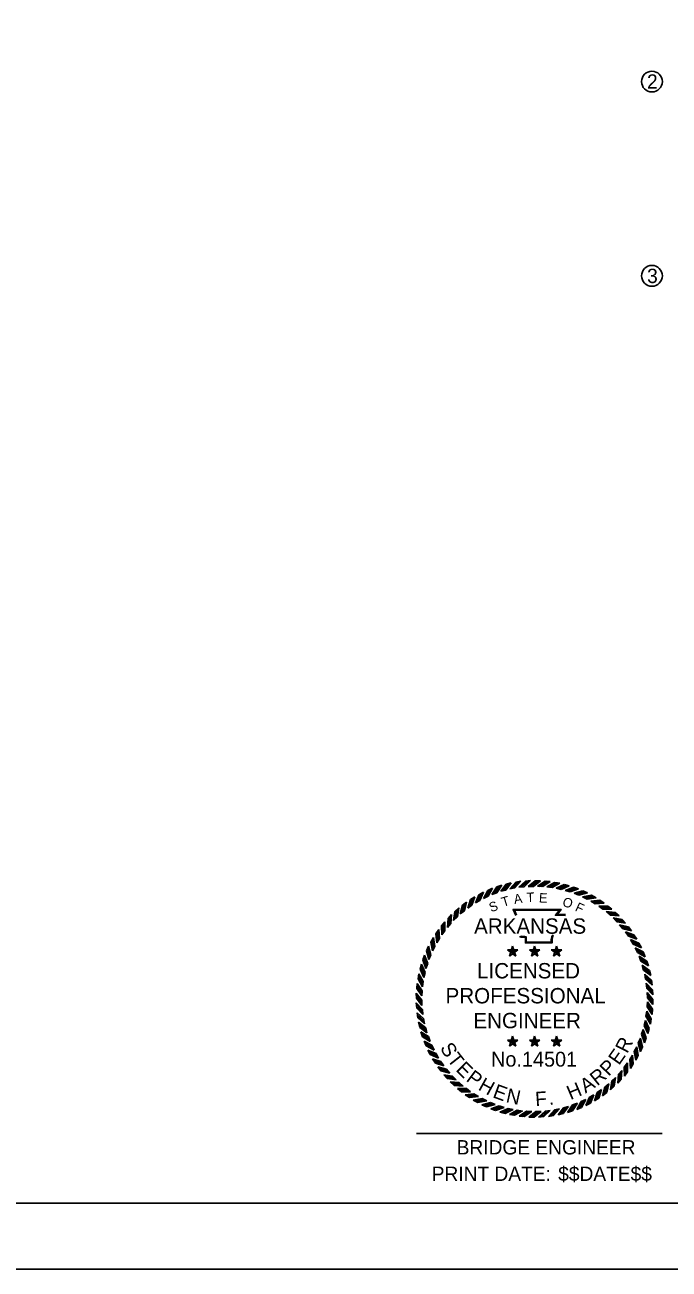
# Model space of a CAD drawing. Extents: x 188 to 14744886, y 129 to 1829278.
# Drawn here: x 208.75 to 214.37, y 128.51 to 139.38 of the extents above; entities that cross this region are included whole.
import ezdxf

# ---------------------------------------------------------------- set-up
doc = ezdxf.new("R2010")
doc.units = 0
for name, color, linetype in [('B_border', 7, 'Continuous'), ('B_Dimensions', 7, 'Continuous'), ('B_Print_Date_Text', 7, 'Continuous'), ('B_StampSFH', 7, 'Continuous'), ('B_Text', 7, 'Continuous'), ('R_Border', 7, 'Continuous'), ('R_No Plot', 7, 'Continuous')]:
    doc.layers.add(name, color=color, linetype=linetype)

msp = doc.modelspace()

# ---------------------------------------------------------------- linework, layer by layer
at = {"layer": 'B_border'}
msp.add_line((212.167, 129.699), (214.309, 129.699), dxfattribs=at)
msp.add_line((212.167, 129.699), (214.309, 129.699), dxfattribs=at)
at = {"layer": 'B_Dimensions'}
for centre in [(214.221, 138.883), (214.221, 137.187)]:
    msp.add_circle(centre, 0.0908, dxfattribs=at)
at = {"layer": 'B_StampSFH'}
for p, q in [((213.033, 131.892), (213.077, 131.9)), ((213.117, 131.902), (213.162, 131.906)), ((213.203, 131.905), (213.248, 131.905)), ((213.288, 131.901), (213.333, 131.898)), ((212.711, 131.783), (212.75, 131.805)), ((212.788, 131.82), (212.829, 131.839)), ((212.825, 131.785), (212.868, 131.8)), ((212.867, 131.851), (212.91, 131.866)), ((212.902, 131.813), (212.946, 131.824)), ((212.949, 131.875), (212.993, 131.886)), ((212.98, 131.834), (213.025, 131.842)), ((213.06, 131.848), (213.105, 131.853)), ((213.141, 131.856), (213.187, 131.856)), ((213.223, 131.858), (213.268, 131.854)), ((213.304, 131.852), (213.349, 131.845)), ((213.372, 131.89), (213.417, 131.883)), ((213.384, 131.84), (213.428, 131.829)), ((213.456, 131.872), (213.5, 131.862)), ((213.464, 131.821), (213.507, 131.807)), ((213.537, 131.848), (213.58, 131.833)), ((213.541, 131.796), (213.583, 131.778)), ((213.617, 131.816), (213.658, 131.798)), ((212.568, 131.691), (212.603, 131.719)), ((212.613, 131.666), (212.65, 131.691)), ((212.637, 131.74), (212.675, 131.765)), ((212.68, 131.711), (212.72, 131.733)), ((212.751, 131.751), (212.792, 131.77)), ((213.616, 131.765), (213.656, 131.743)), ((213.688, 131.727), (213.726, 131.703)), ((213.693, 131.778), (213.733, 131.757)), ((213.757, 131.684), (213.793, 131.656)), ((213.766, 131.734), (213.804, 131.71)), ((213.835, 131.684), (213.871, 131.657)), ((212.442, 131.576), (212.472, 131.61)), ((212.49, 131.559), (212.523, 131.59)), ((212.502, 131.636), (212.535, 131.667)), ((212.549, 131.615), (212.585, 131.643)), ((213.822, 131.635), (213.856, 131.604)), ((213.883, 131.58), (213.914, 131.547)), ((213.9, 131.629), (213.934, 131.599)), ((213.96, 131.568), (213.991, 131.535)), ((212.336, 131.442), (212.361, 131.48)), ((212.386, 131.511), (212.414, 131.547)), ((212.387, 131.433), (212.415, 131.469)), ((212.436, 131.498), (212.467, 131.532)), ((213.939, 131.521), (213.967, 131.486)), ((213.99, 131.458), (214.015, 131.42)), ((214.015, 131.503), (214.043, 131.468)), ((212.292, 131.369), (212.314, 131.409)), ((212.344, 131.364), (212.368, 131.402)), ((214.035, 131.391), (214.057, 131.351)), ((214.064, 131.433), (214.089, 131.396)), ((214.107, 131.36), (214.129, 131.32)), ((212.223, 131.213), (212.237, 131.256)), ((212.255, 131.293), (212.272, 131.334)), ((212.275, 131.217), (212.292, 131.259)), ((212.306, 131.292), (212.327, 131.332)), ((213.051, 131.301), (212.96, 131.301)), ((212.96, 131.301), (213.034, 131.247)), ((213.005, 131.334), (212.977, 131.247)), ((212.977, 131.247), (213.051, 131.301)), ((212.999, 131.286), (213.012, 131.286)), ((213.034, 131.247), (213.005, 131.334)), ((213.005, 131.291), (213.005, 131.279)), ((213.243, 131.301), (213.152, 131.301)), ((213.152, 131.301), (213.225, 131.247)), ((213.197, 131.334), (213.169, 131.247)), ((213.169, 131.247), (213.243, 131.301)), ((213.191, 131.286), (213.204, 131.286)), ((213.225, 131.247), (213.197, 131.334)), ((213.197, 131.291), (213.197, 131.279)), ((213.435, 131.301), (213.343, 131.301)), ((213.344, 131.301), (213.417, 131.247)), ((213.389, 131.334), (213.361, 131.247)), ((213.361, 131.247), (213.435, 131.301)), ((213.383, 131.286), (213.396, 131.286)), ((213.417, 131.247), (213.389, 131.334)), ((213.389, 131.291), (213.389, 131.279)), ((214.075, 131.32), (214.094, 131.278)), ((214.109, 131.246), (214.124, 131.203)), ((214.144, 131.283), (214.163, 131.242)), ((212.198, 131.132), (212.209, 131.176)), ((212.249, 131.14), (212.264, 131.183)), ((214.137, 131.169), (214.148, 131.125)), ((214.175, 131.203), (214.19, 131.161)), ((212.18, 131.048), (212.188, 131.093)), ((212.218, 130.98), (212.226, 131.025)), ((212.231, 131.06), (212.241, 131.104)), ((214.158, 131.09), (214.166, 131.046)), ((214.199, 131.122), (214.21, 131.078)), ((214.216, 131.038), (214.224, 130.993)), ((212.166, 130.879), (212.165, 130.924)), ((212.17, 130.964), (212.173, 131.009)), ((212.213, 130.899), (212.216, 130.944)), ((214.172, 131.01), (214.177, 130.965)), ((214.18, 130.929), (214.181, 130.884)), ((214.226, 130.953), (214.23, 130.908)), ((212.169, 130.793), (212.164, 130.838)), ((212.214, 130.817), (212.214, 130.863)), ((214.182, 130.848), (214.178, 130.803)), ((214.229, 130.868), (214.23, 130.823)), ((212.179, 130.709), (212.171, 130.753)), ((212.222, 130.736), (212.218, 130.782)), ((212.237, 130.656), (212.229, 130.701)), ((214.176, 130.767), (214.169, 130.722)), ((214.214, 130.698), (214.207, 130.654)), ((214.225, 130.783), (214.222, 130.738)), ((212.196, 130.625), (212.184, 130.669)), ((212.258, 130.578), (212.247, 130.622)), ((214.145, 130.607), (214.131, 130.564)), ((214.164, 130.686), (214.153, 130.642)), ((214.196, 130.615), (214.186, 130.571)), ((212.22, 130.543), (212.205, 130.586)), ((212.25, 130.464), (212.232, 130.505)), ((212.286, 130.501), (212.271, 130.544)), ((213.051, 130.514), (212.96, 130.514)), ((212.96, 130.514), (213.034, 130.46)), ((213.005, 130.547), (212.977, 130.46)), ((212.977, 130.46), (213.051, 130.514)), ((212.999, 130.499), (213.012, 130.499)), ((213.034, 130.46), (213.005, 130.547)), ((213.005, 130.504), (213.005, 130.493)), ((213.243, 130.514), (213.152, 130.514)), ((213.152, 130.514), (213.225, 130.46)), ((213.197, 130.547), (213.169, 130.46)), ((213.169, 130.46), (213.243, 130.514)), ((213.191, 130.499), (213.204, 130.499)), ((213.225, 130.46), (213.197, 130.547)), ((213.197, 130.504), (213.197, 130.493)), ((213.435, 130.514), (213.343, 130.514)), ((213.344, 130.514), (213.417, 130.46)), ((213.389, 130.547), (213.361, 130.46)), ((213.361, 130.46), (213.435, 130.514)), ((213.383, 130.499), (213.396, 130.499)), ((213.417, 130.46), (213.389, 130.547)), ((213.389, 130.504), (213.389, 130.493)), ((214.12, 130.53), (214.102, 130.488)), ((214.172, 130.533), (214.157, 130.49)), ((212.287, 130.387), (212.266, 130.427)), ((212.32, 130.427), (212.301, 130.469)), ((212.359, 130.356), (212.337, 130.396)), ((214.051, 130.383), (214.027, 130.344)), ((214.089, 130.455), (214.067, 130.415)), ((214.102, 130.378), (214.081, 130.338)), ((214.14, 130.454), (214.122, 130.413)), ((212.331, 130.313), (212.306, 130.351)), ((212.38, 130.244), (212.352, 130.279)), ((212.405, 130.289), (212.38, 130.327)), ((214.008, 130.314), (213.98, 130.278)), ((214.058, 130.305), (214.034, 130.267)), ((212.435, 130.178), (212.404, 130.211)), ((212.456, 130.225), (212.428, 130.261)), ((212.512, 130.166), (212.481, 130.199)), ((213.904, 130.188), (213.871, 130.157)), ((213.953, 130.171), (213.923, 130.137)), ((213.959, 130.249), (213.928, 130.215)), ((214.008, 130.235), (213.981, 130.2)), ((212.495, 130.118), (212.461, 130.148)), ((212.559, 130.062), (212.523, 130.09)), ((212.573, 130.112), (212.539, 130.143)), ((212.638, 130.063), (212.602, 130.091)), ((213.782, 130.081), (213.744, 130.056)), ((213.827, 130.056), (213.791, 130.028)), ((213.845, 130.132), (213.81, 130.104)), ((213.892, 130.111), (213.859, 130.08)), ((212.629, 130.012), (212.591, 130.037)), ((212.702, 129.968), (212.662, 129.99)), ((212.707, 130.02), (212.668, 130.044)), ((212.778, 129.931), (212.736, 129.948)), ((212.779, 129.982), (212.739, 130.003)), ((212.854, 129.951), (212.812, 129.968)), ((212.931, 129.925), (212.888, 129.94)), ((213.57, 129.962), (213.527, 129.947)), ((213.644, 129.996), (213.602, 129.977)), ((213.684, 129.963), (213.644, 129.942)), ((213.715, 130.035), (213.675, 130.014)), ((213.757, 130.007), (213.72, 129.982)), ((212.857, 129.899), (212.814, 129.914)), ((212.939, 129.874), (212.895, 129.885)), ((213.01, 129.907), (212.966, 129.917)), ((213.022, 129.857), (212.978, 129.864)), ((213.091, 129.894), (213.046, 129.902)), ((213.107, 129.846), (213.062, 129.849)), ((213.172, 129.889), (213.127, 129.892)), ((213.192, 129.842), (213.147, 129.841)), ((213.253, 129.89), (213.208, 129.89)), ((213.277, 129.845), (213.232, 129.841)), ((213.334, 129.898), (213.289, 129.894)), ((213.362, 129.855), (213.317, 129.847)), ((213.414, 129.913), (213.37, 129.905)), ((213.446, 129.872), (213.402, 129.86)), ((213.493, 129.934), (213.449, 129.923)), ((213.527, 129.896), (213.485, 129.881)), ((213.607, 129.926), (213.566, 129.908))]:
    msp.add_line(p, q, dxfattribs=at)
for points in [[(212.995, 131.836), (213.047, 131.894)], [(213.01, 131.839), (213.062, 131.897)], [(213.025, 131.842), (213.077, 131.9)], [(213.06, 131.848), (213.117, 131.902)], [(213.075, 131.85), (213.132, 131.903)], [(213.09, 131.851), (213.147, 131.905)], [(213.105, 131.853), (213.162, 131.906)], [(213.141, 131.856), (213.203, 131.905)], [(213.156, 131.856), (213.218, 131.904)], [(213.172, 131.857), (213.233, 131.905)], [(213.187, 131.856), (213.248, 131.905)], [(213.223, 131.858), (213.288, 131.901)], [(213.237, 131.856), (213.302, 131.9)], [(213.253, 131.856), (213.318, 131.899)], [(213.268, 131.854), (213.333, 131.898)], [(212.693, 131.718), (212.724, 131.79)], [(212.707, 131.726), (212.737, 131.798)], [(212.72, 131.733), (212.751, 131.805)], [(212.751, 131.751), (212.788, 131.82)], [(212.764, 131.757), (212.801, 131.826)], [(212.779, 131.764), (212.815, 131.833)], [(212.792, 131.77), (212.829, 131.839)], [(212.825, 131.785), (212.867, 131.851)], [(212.839, 131.79), (212.881, 131.856)], [(212.854, 131.795), (212.896, 131.861)], [(212.868, 131.8), (212.91, 131.866)], [(212.902, 131.813), (212.949, 131.875)], [(212.916, 131.816), (212.963, 131.878)], [(212.931, 131.82), (212.978, 131.883)], [(212.945, 131.824), (212.993, 131.886)], [(212.98, 131.834), (213.033, 131.892)], [(213.304, 131.852), (213.372, 131.89)], [(213.318, 131.85), (213.387, 131.888)], [(213.334, 131.848), (213.402, 131.886)], [(213.349, 131.845), (213.417, 131.883)], [(213.384, 131.84), (213.456, 131.872)], [(213.398, 131.837), (213.47, 131.869)], [(213.414, 131.833), (213.485, 131.865)], [(213.428, 131.829), (213.5, 131.862)], [(213.463, 131.821), (213.537, 131.848)], [(213.477, 131.817), (213.551, 131.843)], [(213.492, 131.812), (213.566, 131.838)], [(213.507, 131.807), (213.58, 131.833)], [(213.541, 131.796), (213.617, 131.816)], [(213.554, 131.79), (213.63, 131.81)], [(213.569, 131.784), (213.644, 131.804)], [(213.583, 131.778), (213.658, 131.798)], [(212.549, 131.615), (212.568, 131.691)], [(212.561, 131.624), (212.579, 131.7)], [(212.573, 131.634), (212.591, 131.71)], [(212.585, 131.643), (212.603, 131.719)], [(212.613, 131.666), (212.637, 131.74)], [(212.625, 131.674), (212.65, 131.748)], [(212.638, 131.683), (212.662, 131.757)], [(212.65, 131.691), (212.675, 131.765)], [(212.68, 131.711), (212.711, 131.783)], [(213.616, 131.765), (213.693, 131.778)], [(213.629, 131.758), (213.706, 131.771)], [(213.643, 131.751), (213.72, 131.764)], [(213.656, 131.743), (213.733, 131.757)], [(213.688, 131.727), (213.766, 131.734)], [(213.7, 131.719), (213.778, 131.726)], [(213.714, 131.711), (213.792, 131.718)], [(213.726, 131.703), (213.804, 131.71)], [(213.757, 131.684), (213.835, 131.684)], [(213.768, 131.675), (213.847, 131.675)], [(212.436, 131.498), (212.442, 131.576)], [(212.446, 131.509), (212.452, 131.587)], [(212.456, 131.521), (212.462, 131.599)], [(212.466, 131.532), (212.472, 131.61)], [(212.49, 131.559), (212.502, 131.636)], [(212.501, 131.569), (212.513, 131.646)], [(212.512, 131.58), (212.524, 131.657)], [(212.523, 131.59), (212.535, 131.667)], [(213.034, 131.602), (213.01, 131.654), (213.428, 131.654), (213.393, 131.61), (213.421, 131.611), (213.445, 131.611), (213.468, 131.609)], [(213.04, 131.605), (213.021, 131.647), (213.414, 131.648), (213.379, 131.604), (213.421, 131.604), (213.444, 131.605), (213.468, 131.602)], [(213.781, 131.665), (213.859, 131.666)], [(213.793, 131.656), (213.871, 131.657)], [(213.822, 131.635), (213.9, 131.629)], [(213.833, 131.625), (213.911, 131.619)], [(213.844, 131.614), (213.923, 131.609)], [(213.856, 131.604), (213.934, 131.599)], [(213.883, 131.58), (213.96, 131.568)], [(213.892, 131.57), (213.97, 131.558)], [(212.36, 131.39), (212.353, 131.468)], [(212.368, 131.402), (212.361, 131.48)], [(212.387, 131.433), (212.386, 131.511)], [(212.396, 131.444), (212.395, 131.523)], [(212.405, 131.457), (212.405, 131.535)], [(212.415, 131.469), (212.414, 131.547)], [(213.903, 131.558), (213.981, 131.546)], [(213.914, 131.547), (213.991, 131.535)], [(213.939, 131.521), (214.015, 131.503)], [(213.948, 131.51), (214.024, 131.491)], [(213.958, 131.498), (214.034, 131.479)], [(213.967, 131.486), (214.043, 131.468)], [(213.99, 131.458), (214.064, 131.433)], [(212.306, 131.292), (212.292, 131.369)], [(212.313, 131.305), (212.299, 131.382)], [(212.32, 131.319), (212.306, 131.396)], [(212.327, 131.332), (212.314, 131.409)], [(212.344, 131.364), (212.336, 131.442)], [(212.352, 131.376), (212.344, 131.454)], [(213.362, 131.427), (213.355, 131.421), (213.352, 131.413), (213.35, 131.391), (213.35, 131.362), (213.117, 131.362), (213.117, 131.401), (213.117, 131.41), (213.108, 131.413), (213.075, 131.413), (213.069, 131.422)], [(213.358, 131.432), (213.349, 131.425), (213.346, 131.414), (213.343, 131.391), (213.343, 131.369), (213.124, 131.369), (213.124, 131.401), (213.124, 131.415), (213.109, 131.419), (213.078, 131.419), (213.074, 131.425)], [(213.998, 131.446), (214.072, 131.421)], [(214.007, 131.433), (214.081, 131.408)], [(214.015, 131.42), (214.089, 131.396)], [(214.035, 131.391), (214.107, 131.36)], [(214.042, 131.378), (214.114, 131.347)], [(214.05, 131.364), (214.122, 131.333)], [(214.057, 131.351), (214.129, 131.32)], [(212.259, 131.168), (212.233, 131.242)], [(212.264, 131.183), (212.237, 131.256)], [(212.275, 131.217), (212.255, 131.293)], [(212.28, 131.23), (212.26, 131.306)], [(212.286, 131.245), (212.266, 131.321)], [(212.292, 131.259), (212.272, 131.334)], [(214.075, 131.32), (214.144, 131.283)], [(214.081, 131.306), (214.15, 131.27)], [(214.088, 131.292), (214.157, 131.256)], [(214.094, 131.278), (214.163, 131.242)], [(214.109, 131.246), (214.175, 131.203)], [(212.231, 131.06), (212.198, 131.132)], [(212.234, 131.074), (212.202, 131.146)], [(212.238, 131.09), (212.205, 131.161)], [(212.241, 131.104), (212.209, 131.176)], [(212.249, 131.14), (212.223, 131.213)], [(212.254, 131.153), (212.228, 131.227)], [(214.114, 131.232), (214.18, 131.19)], [(214.119, 131.217), (214.185, 131.175)], [(214.124, 131.203), (214.19, 131.161)], [(214.137, 131.169), (214.199, 131.122)], [(214.14, 131.155), (214.202, 131.108)], [(214.144, 131.14), (214.207, 131.092)], [(212.218, 130.98), (212.181, 131.048)], [(212.221, 130.994), (212.183, 131.063)], [(212.223, 131.01), (212.185, 131.078)], [(212.225, 131.025), (212.188, 131.093)], [(214.148, 131.125), (214.21, 131.078)], [(214.158, 131.09), (214.216, 131.038)], [(214.16, 131.076), (214.218, 131.024)], [(214.163, 131.061), (214.221, 131.008)], [(214.166, 131.046), (214.224, 130.993)], [(212.214, 130.863), (212.165, 130.924)], [(212.213, 130.899), (212.17, 130.964)], [(212.214, 130.913), (212.171, 130.978)], [(212.215, 130.929), (212.172, 130.994)], [(212.216, 130.944), (212.173, 131.009)], [(214.172, 131.01), (214.226, 130.953)], [(214.174, 130.996), (214.227, 130.939)], [(214.175, 130.98), (214.229, 130.923)], [(214.177, 130.965), (214.23, 130.908)], [(214.18, 130.929), (214.229, 130.868)], [(214.18, 130.915), (214.229, 130.854)], [(212.218, 130.781), (212.164, 130.839)], [(212.214, 130.848), (212.165, 130.909)], [(212.214, 130.832), (212.166, 130.893)], [(212.214, 130.817), (212.166, 130.879)], [(212.219, 130.766), (212.166, 130.823)], [(212.221, 130.751), (212.167, 130.808)], [(214.18, 130.834), (214.224, 130.768)], [(214.18, 130.818), (214.223, 130.753)], [(214.181, 130.899), (214.23, 130.838)], [(214.181, 130.884), (214.23, 130.823)], [(214.182, 130.848), (214.225, 130.783)], [(212.222, 130.736), (212.169, 130.793)], [(212.229, 130.701), (212.171, 130.753)], [(212.231, 130.686), (212.173, 130.738)], [(212.235, 130.671), (212.176, 130.723)], [(212.237, 130.656), (212.179, 130.709)], [(214.169, 130.722), (214.207, 130.654)], [(214.172, 130.737), (214.21, 130.668)], [(214.174, 130.753), (214.212, 130.684)], [(214.176, 130.767), (214.214, 130.698)], [(214.178, 130.803), (214.222, 130.738)], [(212.247, 130.622), (212.184, 130.669)], [(212.25, 130.607), (212.188, 130.654)], [(212.255, 130.592), (212.192, 130.639)], [(212.258, 130.578), (212.196, 130.625)], [(214.141, 130.593), (214.167, 130.52)], [(214.145, 130.607), (214.171, 130.533)], [(214.153, 130.642), (214.186, 130.571)], [(214.157, 130.657), (214.189, 130.586)], [(214.16, 130.672), (214.193, 130.601)], [(214.164, 130.686), (214.196, 130.615)], [(212.271, 130.544), (212.205, 130.586)], [(212.275, 130.53), (212.21, 130.572)], [(212.281, 130.515), (212.215, 130.557)], [(212.286, 130.501), (212.22, 130.543)], [(212.301, 130.468), (212.232, 130.505)], [(212.307, 130.455), (212.238, 130.491)], [(214.102, 130.488), (214.122, 130.412)], [(214.108, 130.502), (214.128, 130.426)], [(214.114, 130.517), (214.134, 130.441)], [(214.12, 130.53), (214.14, 130.454)], [(214.131, 130.564), (214.157, 130.49)], [(214.136, 130.578), (214.162, 130.505)], [(212.314, 130.44), (212.245, 130.477)], [(212.32, 130.427), (212.25, 130.464)], [(212.337, 130.396), (212.265, 130.427)], [(212.345, 130.383), (212.273, 130.413)], [(212.353, 130.369), (212.281, 130.4)], [(212.359, 130.356), (212.287, 130.387)], [(214.051, 130.383), (214.058, 130.305)], [(214.067, 130.415), (214.081, 130.338)], [(214.075, 130.428), (214.088, 130.351)], [(214.082, 130.442), (214.095, 130.365)], [(214.089, 130.455), (214.102, 130.378)], [(212.38, 130.326), (212.306, 130.351)], [(212.388, 130.314), (212.314, 130.338)], [(212.397, 130.301), (212.323, 130.326)], [(212.405, 130.289), (212.331, 130.313)], [(212.428, 130.261), (212.352, 130.279)], [(212.437, 130.249), (212.361, 130.267)], [(213.98, 130.278), (213.981, 130.199)], [(213.989, 130.29), (213.99, 130.211)], [(213.999, 130.302), (213.999, 130.224)], [(214.008, 130.314), (214.008, 130.236)], [(214.027, 130.344), (214.034, 130.266)], [(214.035, 130.357), (214.042, 130.279)], [(214.043, 130.37), (214.05, 130.293)], [(212.447, 130.237), (212.371, 130.255)], [(212.456, 130.225), (212.38, 130.244)], [(212.481, 130.199), (212.404, 130.211)], [(212.491, 130.188), (212.414, 130.2)], [(212.502, 130.177), (212.425, 130.189)], [(212.512, 130.166), (212.435, 130.178)], [(213.871, 130.157), (213.859, 130.08)], [(213.882, 130.167), (213.87, 130.09)], [(213.894, 130.178), (213.882, 130.101)], [(213.904, 130.188), (213.892, 130.111)], [(213.928, 130.215), (213.923, 130.137)], [(213.938, 130.226), (213.933, 130.148)], [(213.949, 130.238), (213.943, 130.16)], [(213.959, 130.249), (213.953, 130.171)], [(212.539, 130.143), (212.461, 130.148)], [(212.55, 130.132), (212.472, 130.138)], [(212.562, 130.122), (212.484, 130.128)], [(212.573, 130.112), (212.495, 130.118)], [(212.602, 130.091), (212.523, 130.09)], [(212.614, 130.081), (212.535, 130.081)], [(212.626, 130.072), (212.548, 130.071)], [(212.638, 130.063), (212.56, 130.062)], [(213.744, 130.056), (213.72, 129.982)], [(213.757, 130.064), (213.732, 129.99)], [(213.77, 130.073), (213.745, 129.999)], [(213.782, 130.081), (213.757, 130.007)], [(213.81, 130.104), (213.791, 130.028)], [(213.822, 130.113), (213.803, 130.037)], [(213.834, 130.123), (213.815, 130.047)], [(213.845, 130.132), (213.827, 130.056)], [(212.668, 130.044), (212.59, 130.037)], [(212.681, 130.036), (212.603, 130.029)], [(212.694, 130.028), (212.616, 130.02)], [(212.707, 130.02), (212.629, 130.012)], [(212.739, 130.003), (212.662, 129.99)], [(212.752, 129.996), (212.675, 129.982)], [(212.766, 129.989), (212.689, 129.975)], [(212.779, 129.982), (212.702, 129.968)], [(212.812, 129.968), (212.736, 129.948)], [(212.826, 129.962), (212.75, 129.942)], [(212.84, 129.956), (212.765, 129.936)], [(212.854, 129.951), (212.778, 129.931)], [(212.888, 129.94), (212.814, 129.913)], [(213.527, 129.947), (213.485, 129.881)], [(213.541, 129.952), (213.499, 129.886)], [(213.556, 129.957), (213.514, 129.891)], [(213.57, 129.962), (213.527, 129.896)], [(213.602, 129.977), (213.566, 129.908)], [(213.616, 129.983), (213.579, 129.914)], [(213.63, 129.99), (213.594, 129.921)], [(213.644, 129.996), (213.607, 129.926)], [(213.675, 130.014), (213.644, 129.942)], [(213.688, 130.021), (213.657, 129.949)], [(213.702, 130.029), (213.671, 129.957)], [(213.715, 130.036), (213.684, 129.964)], [(212.902, 129.935), (212.829, 129.909)], [(212.917, 129.93), (212.844, 129.904)], [(212.931, 129.925), (212.857, 129.899)], [(212.966, 129.917), (212.895, 129.885)], [(212.981, 129.914), (212.91, 129.881)], [(212.996, 129.91), (212.925, 129.878)], [(213.01, 129.907), (212.939, 129.874)], [(213.046, 129.902), (212.978, 129.864)], [(213.061, 129.899), (212.992, 129.861)], [(213.076, 129.897), (213.008, 129.859)], [(213.091, 129.895), (213.022, 129.857)], [(213.127, 129.892), (213.062, 129.849)], [(213.142, 129.891), (213.077, 129.848)], [(213.158, 129.89), (213.092, 129.847)], [(213.172, 129.889), (213.107, 129.846)], [(213.208, 129.89), (213.147, 129.841)], [(213.223, 129.89), (213.162, 129.841)], [(213.239, 129.89), (213.178, 129.842)], [(213.253, 129.89), (213.192, 129.842)], [(213.289, 129.894), (213.232, 129.84)], [(213.304, 129.895), (213.247, 129.842)], [(213.32, 129.897), (213.263, 129.844)], [(213.334, 129.898), (213.277, 129.845)], [(213.37, 129.905), (213.317, 129.847)], [(213.385, 129.908), (213.332, 129.849)], [(213.4, 129.911), (213.348, 129.852)], [(213.414, 129.913), (213.362, 129.855)], [(213.449, 129.923), (213.402, 129.86)], [(213.464, 129.926), (213.416, 129.864)], [(213.479, 129.931), (213.431, 129.868)], [(213.493, 129.934), (213.446, 129.872)]]:
    msp.add_lwpolyline(points, dxfattribs=at)
at = {"layer": 'R_Border'}
msp.add_line((221.306, 129.091), (189.399, 129.091), dxfattribs=at)
at = {"layer": 'R_No Plot'}
msp.add_lwpolyline([(187.883, 150.514), (221.883, 150.514), (221.883, 128.514), (187.883, 128.514)], close=True, dxfattribs=at)

# ---------------------------------------------------------------- texts
at = {"layer": 'B_Print_Date_Text'}
msp.add_text('PRINT DATE:', height=0.125, dxfattribs=at).set_placement((212.299, 129.284))
msp.add_text('$$DATE$$', height=0.125, rotation=359.9999, dxfattribs=at).set_placement((213.403, 129.284))
at = {"layer": 'B_StampSFH'}
for s, height, rotation, p in [('A', 0.0823, 8.6788, (213.022, 131.702)), ('T', 0.0823, 1.4789, (213.128, 131.719)), ('E', 0.0823, 356.672, (213.233, 131.716)), ('S', 0.0823, 19.7726, (212.817, 131.629)), ('T', 0.0823, 16.9015, (212.922, 131.676)), ('O', 0.0823, 341.2218, (213.433, 131.688)), ('F', 0.0823, 335.3628, (213.544, 131.645)), ('S', 0.125, 300.7985, (212.368, 130.446)), ('R', 0.125, 62.6418, (214.005, 130.391)), ('T', 0.125, 308.0945, (212.429, 130.343)), ('E', 0.125, 54.981, (213.933, 130.288)), ('E', 0.125, 315.3905, (212.503, 130.25)), ('P', 0.125, 46.9554, (213.844, 130.192)), ('P', 0.125, 323.0513, (212.592, 130.162)), ('H', 0.125, 331.0769, (212.697, 130.084)), ('A', 0.125, 31.6338, (213.641, 130.046)), ('R', 0.125, 38.9298, (213.743, 130.109)), ('E', 0.125, 339.8321, (212.824, 130.016)), ('N', 0.125, 347.4929, (212.941, 129.973)), ('F', 0.125, 3.9089, (213.206, 129.936)), ('H', 0.125, 22.8786, (213.51, 129.989)), ('.', 0.125, 11.205, (213.325, 129.945))]:
    msp.add_text(s, height=height, rotation=rotation, dxfattribs=at).set_placement(p)
for s, height, p in [('ARKANSAS', 0.1343, (212.669, 131.442)), ('LICENSED', 0.1343, (212.695, 131.052)), ('PROFESSIONAL', 0.13433, (212.42, 130.834)), ('ENGINEER', 0.1343, (212.663, 130.617)), ('No.14501', 0.1295, (212.817, 130.282))]:
    msp.add_text(s, height=height, dxfattribs=at).set_placement(p)
at = {"layer": 'B_Text'}
for s, p in [('2', (214.178, 138.821)), ('3', (214.179, 137.124)), ('BRIDGE ENGINEER', (212.517, 129.515))]:
    msp.add_text(s, height=0.125, dxfattribs=at).set_placement(p)

doc.saveas('drawing.dxf')
